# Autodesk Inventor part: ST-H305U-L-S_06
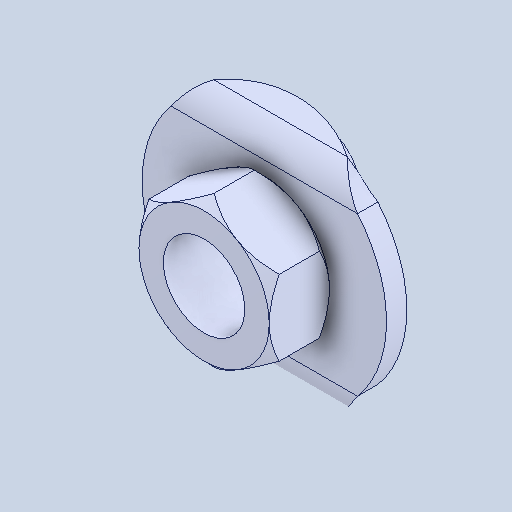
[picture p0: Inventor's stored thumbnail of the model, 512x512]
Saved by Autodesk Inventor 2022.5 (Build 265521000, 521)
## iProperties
Created: 2024-07
Part Number: ST-H305U-L-S_06
Material: 一般
Document SubType Name: Modeling
Designer: ImaoCorp
Density: 1 g/cm^3
Appearance: 既定
Author: ImaoCorp
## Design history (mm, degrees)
feature "ST-H305U-L-S_06"
node "ソリッド1"
